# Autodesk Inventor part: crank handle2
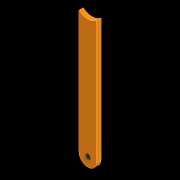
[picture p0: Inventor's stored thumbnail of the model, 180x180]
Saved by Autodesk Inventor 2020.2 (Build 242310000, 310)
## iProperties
Category: 11
Manager: PART
Company: 22
Created: 2020-10
Part Number: crank handle2
Material: Generic
Document SubType Name: Modeling
Designer: Apardo
Density: 1 g/cm^3
Appearance: Orange
Vendor: 11
Project: PLATE ROLLING MACHINE
Engineer: STEEL C45
Stock Number: 2.2
Engr Approved By: D. JAEGER
Author: Apardo
Revision Number: 1.0
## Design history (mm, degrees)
sketch "Sketch1"
  geometry: L1 (-10, -80)-(12.835, -80); L2 (10, -70)-(10, 68.82); L3 (-10, 68.82)-(-10, -70); L4 (-10, -80)-(8.77, 70.159); L5 (12.835, -80)-(-11.229, 69.995); A1 r 15 centre (0, 80) between (-10, 68.82) and (10, 68.82); A2 r 10 centre (0, -70) between (-10, -70) and (10, -70); 1 further point
  constraints: 10 end point, 4 point on circle, 3 tangent, 2 centre point, 2 point on line, 1 horizontal, 1 parallel, 1 perpendicular
  dimensions: "d0" = 20 distance of L4.end L5.end; "d1" = 30 diameter of A1; "d3" = 160 distance from line of L1 A1.centre; "d4" = 10 distance from line of point (0, 0) L3 (= 0.5 x d0); "d5" = 80 distance from line of point (0, 0) L1 (= 0.5 x d3)
extrude "Extrusion1" new body sketch "Sketch1" stored distance "d6" = 5; taper "d7" = 0 deg
sketch "Sketch2"
  geometry: A1 r 10 centre (0, -70) between (-10, -70) and (10, -70) reference; 2 further points
  constraints: 1 coincident
hole "Hole1" sketch "Sketch2" at (0, -70) diameter "d8" = 6.647; stored, may be unused: countersink angle "d12" = 90 deg, drill point angle "d14" = 118 deg; dims "d9" = 5, "d10" = 4, "d11" = 2, "d13" = 22.2
body "Solid1"
